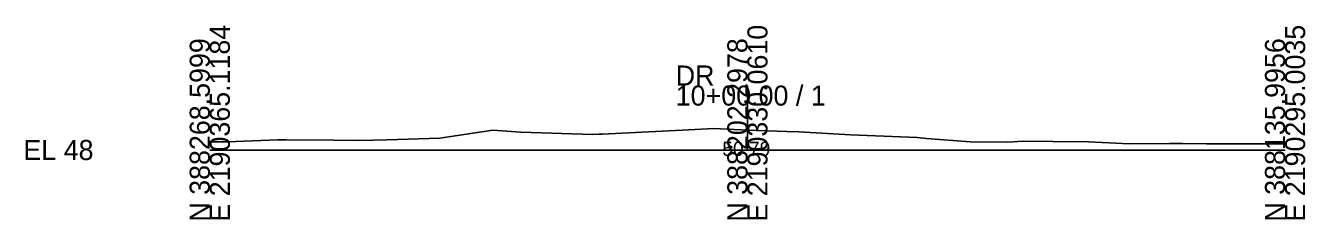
# Model space of a CAD drawing. Extents: x -26 to 153, y -10 to 1035.
# Drawn here: x -25.7 to 152.8, y -9.7 to 17.4 of the extents above; entities that cross this region are included whole.
import ezdxf

# ---------------------------------------------------------------- set-up
doc = ezdxf.new("R2010")
doc.units = 0
for name, color, linetype in [('Default', 7, 'Continuous'), ('Exist CMT Ground Line', 7, 'Continuous'), ('Exist Cross Section Cell', 7, 'Continuous'), ('Exist XS Center Line Elevation Label', 7, 'Continuous')]:
    doc.layers.add(name, color=color, linetype=linetype)

msp = doc.modelspace()

# ---------------------------------------------------------------- linework, layer by layer
at = {"layer": 'Exist CMT Ground Line'}
for p, q in [((32.1, 1.63), (39.48, 2.78)), ((39.48, 2.78), (43.41, 2.47)), ((43.41, 2.47), (53.44, 2.15)), ((53.44, 2.15), (54.28, 2.22)), ((54.28, 2.22), (54.73, 2.21)), ((54.73, 2.21), (66.81, 2.8)), ((66.81, 2.8), (70.33, 3)), ((70.33, 3), (75, 2.79)), ((75, 2.79), (77.76, 2.67)), ((77.76, 2.67), (80.49, 2.57)), ((80.49, 2.57), (82.17, 2.53)), ((82.17, 2.53), (89.38, 2.13)), ((89.38, 2.13), (98.68, 1.75)), ((0, 1.12), (2.48, 1.14)), ((2.48, 1.14), (9.47, 1.41)), ((9.47, 1.41), (9.88, 1.43)), ((9.88, 1.43), (10.65, 1.42)), ((10.65, 1.42), (17.28, 1.36)), ((17.28, 1.36), (20.79, 1.35)), ((20.79, 1.35), (24.68, 1.42)), ((24.68, 1.42), (32.1, 1.63)), ((98.68, 1.75), (99.98, 1.61)), ((99.98, 1.61), (106.08, 1.13)), ((106.08, 1.13), (111.29, 1.09)), ((111.29, 1.09), (113.48, 1.22)), ((113.48, 1.22), (117.62, 1.21)), ((117.62, 1.21), (122.6, 1.13)), ((122.6, 1.13), (128.28, 0.84)), ((128.28, 0.84), (133.92, 0.92)), ((133.92, 0.92), (135.68, 0.91)), ((135.68, 0.91), (139.02, 0.88)), ((139.02, 0.88), (143.08, 0.87)), ((143.08, 0.87), (145.23, 0.87)), ((145.23, 0.87), (150, 0.84))]:
    msp.add_line(p, q, dxfattribs=at)
at = {"layer": 'Exist Cross Section Cell'}
for p, q in [((75, 0), (75, 9)), ((0, 0), (75, 0)), ((75, 0), (150, 0))]:
    msp.add_line(p, q, dxfattribs=at)

# ---------------------------------------------------------------- texts
at = {"layer": 'Default'}
msp.add_text('-', height=0.0001, dxfattribs=at).set_placement((0, 0))
at = {"layer": 'Exist Cross Section Cell'}
for s, p in [('E 2190365.1184', (2.8, -10)), ('E 2190330.0610', (77.8, -10)), ('E 2190295.0035', (152.8, -10)), ('N 388268.5999', (0, -10)), ('N 388202.2978', (75, -10)), ('N 388135.9956', (150, -10))]:
    msp.add_text(s, height=2.8, rotation=90, dxfattribs=at).set_placement(p)
for s, p in [('DR', (65, 9)), ('10+00.00 / 1', (65, 6.2)), ('EL 48', (-26, -1.4))]:
    msp.add_text(s, height=2.8, dxfattribs=at).set_placement(p)
at = {"layer": 'Exist XS Center Line Elevation Label'}
msp.add_text('50.79', height=2, dxfattribs=at).set_placement((71.5, -0.83))

doc.saveas('drawing.dxf')
